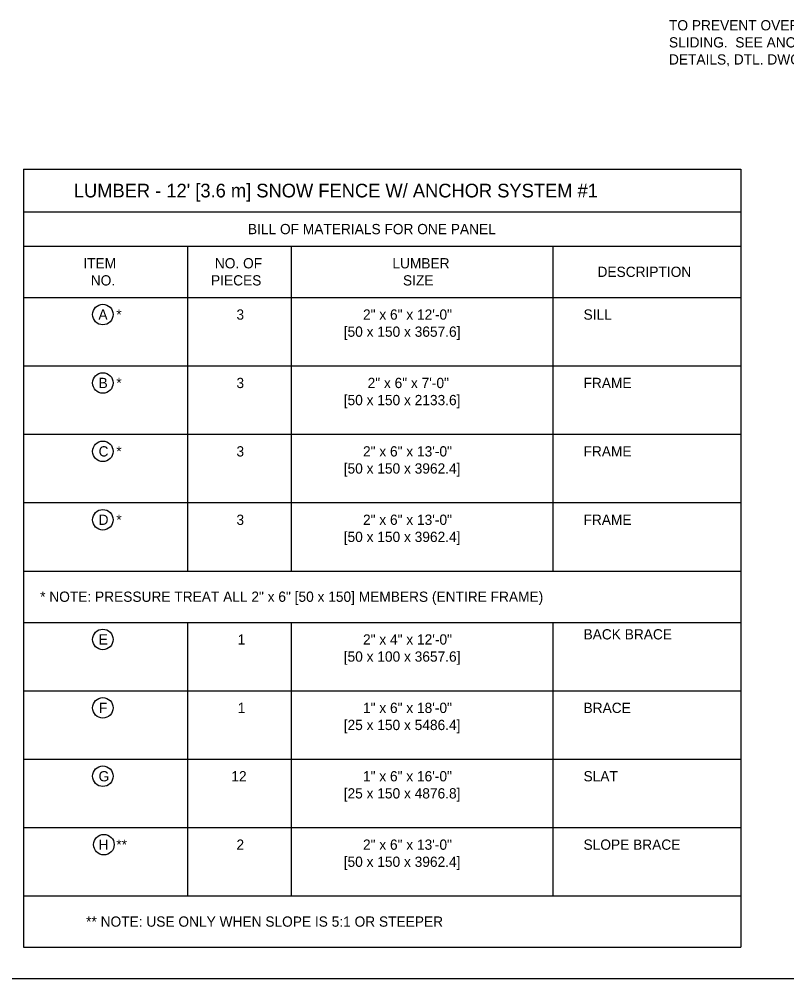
# Model space of a CAD drawing. Extents: x 49991.4 to 50021, y 49987.6 to 50011.4.
# Drawn here: x 50005.06 to 50009.55, y 49987.8 to 49993.41 of the extents above; entities that cross this region are included whole.
import ezdxf

# ---------------------------------------------------------------- set-up
doc = ezdxf.new("R2010")
doc.units = 0
doc.layers.add('Level 1', color=7, linetype='Continuous')
doc.layers.add('Level 2', color=7, linetype='Continuous')

msp = doc.modelspace()

# ---------------------------------------------------------------- linework, layer by layer
at = {"layer": 'Level 1'}
msp.add_lwpolyline([(49999.3835, 49998.9992), (50016.7501, 49998.9992), (50016.7501, 49987.7988), (49999.3835, 49987.7988)], close=True, dxfattribs=at)
at = {"layer": 'Level 2'}
for p, q in [((50005.0866, 49992.5334), (50005.0866, 49987.9834)), ((50005.0866, 49992.5334), (50009.2816, 49992.5334)), ((50009.2816, 49992.5334), (50009.2816, 49987.9834)), ((50005.0866, 49992.2834), (50009.2816, 49992.2834)), ((50005.0866, 49992.0834), (50009.2816, 49992.0834)), ((50006.0473, 49992.0834), (50006.0473, 49990.1834)), ((50006.6522, 49992.0834), (50006.6522, 49990.1834)), ((50008.1833, 49992.0834), (50008.1833, 49990.1834)), ((50005.0866, 49991.7834), (50009.2816, 49991.7834)), ((50005.0866, 49991.3834), (50009.2816, 49991.3834)), ((50005.0866, 49990.9834), (50009.2816, 49990.9834)), ((50005.0866, 49990.5834), (50009.2816, 49990.5834)), ((50005.0866, 49990.1834), (50009.2816, 49990.1834)), ((50005.0866, 49989.8834), (50009.2816, 49989.8834)), ((50006.0473, 49989.8834), (50006.0473, 49988.2834)), ((50006.6522, 49989.8834), (50006.6522, 49988.2834)), ((50008.1833, 49989.8834), (50008.1833, 49988.2834)), ((50005.0866, 49989.4834), (50009.2816, 49989.4834)), ((50005.0866, 49989.0834), (50009.2816, 49989.0834)), ((50005.0866, 49988.6834), (50009.2816, 49988.6834)), ((50005.0866, 49988.2834), (50009.2816, 49988.2834)), ((50005.0866, 49987.9834), (50009.2816, 49987.9834))]:
    msp.add_line(p, q, dxfattribs=at)
for centre in [(50005.5515, 49991.6834), (50005.5516, 49991.2834), (50005.5516, 49990.8834), (50005.5516, 49990.4834), (50005.5516, 49989.7834), (50005.5516, 49989.3834), (50005.5516, 49988.9834), (50005.5577, 49988.5834)]:
    msp.add_circle(centre, 0.06, dxfattribs=at)

# ---------------------------------------------------------------- texts
for s, height, p in [('TO PREVENT OVERTURNING AND', 0.06, (50008.8615, 49993.3453)), ('SLIDING.  SEE ANCHOR SYSTEM #1', 0.06, (50008.8615, 49993.2453)), ('DETAILS, DTL. DWG. NO. 607-40.', 0.06, (50008.8615, 49993.1453)), ("LUMBER - 12' [3.6 m] SNOW FENCE W/ ANCHOR SYSTEM #1", 0.08, (50005.382, 49992.3684)), ('BILL OF MATERIALS FOR ONE PANEL', 0.06, (50006.3998, 49992.1534)), ('ITEM', 0.06, (50005.4374, 49991.9534)), ('NO. OF', 0.06, (50006.2064, 49991.9534)), ('LUMBER', 0.06, (50007.2444, 49991.9534)), ('DESCRIPTION', 0.06, (50008.4436, 49991.9034)), ('NO.', 0.06, (50005.4807, 49991.8534)), ('PIECES', 0.06, (50006.1839, 49991.8534)), ('SIZE', 0.06, (50007.3063, 49991.8534)), ('A', 0.06, (50005.5257, 49991.6534)), ('*', 0.06, (50005.6303, 49991.6534)), ('3', 0.06, (50006.3327, 49991.6534)), ('2" x 6" x 12\'-0"', 0.06, (50007.0727, 49991.6534)), ('SILL         ', 0.06, (50008.3619, 49991.6534)), ('[50 x 150 x 3657.6]', 0.06, (50006.96, 49991.5534)), ('B', 0.06, (50005.5266, 49991.2534)), ('*', 0.06, (50005.6303, 49991.2534)), ('3', 0.06, (50006.3327, 49991.2534)), ('2" x 6" x 7\'-0"', 0.06, (50007.0996, 49991.2534)), ('FRAME        ', 0.06, (50008.3619, 49991.2534)), ('[50 x 150 x 2133.6]', 0.06, (50006.9599, 49991.1534)), ('C', 0.06, (50005.5266, 49990.8534)), ('*', 0.06, (50005.6303, 49990.8534)), ('3', 0.06, (50006.3327, 49990.8534)), ('2" x 6" x 13\'-0"', 0.06, (50007.0726, 49990.8534)), ('FRAME        ', 0.06, (50008.3619, 49990.8534)), ('[50 x 150 x 3962.4]', 0.06, (50006.9599, 49990.7534)), ('D', 0.06, (50005.5266, 49990.4534)), ('*', 0.06, (50005.6303, 49990.4534)), ('3', 0.06, (50006.3327, 49990.4534)), ('2" x 6" x 13\'-0"', 0.06, (50007.0726, 49990.4534)), ('FRAME        ', 0.06, (50008.3619, 49990.4534)), ('[50 x 150 x 3962.4]', 0.06, (50006.9599, 49990.3534)), ('* NOTE: PRESSURE TREAT ALL 2" x 6" [50 x 150] MEMBERS (ENTIRE FRAME)', 0.06, (50005.1848, 49990.0034)), ('BACK BRACE        ', 0.06, (50008.3619, 49989.7834)), ('E', 0.06, (50005.5268, 49989.7534)), ('1', 0.06, (50006.34, 49989.7534)), ('2" x 4" x 12\'-0"', 0.06, (50007.0727, 49989.7534)), ('[50 x 100 x 3657.6]', 0.06, (50006.96, 49989.6534)), ('F', 0.06, (50005.5281, 49989.3534)), ('1', 0.06, (50006.3401, 49989.3534)), ('1" x 6" x 18\'-0"', 0.06, (50007.0726, 49989.3534)), ('BRACE        ', 0.06, (50008.3619, 49989.3534)), ('[25 x 150 x 5486.4]', 0.06, (50006.9599, 49989.2534)), ('G', 0.06, (50005.5266, 49988.9534)), ('12', 0.06, (50006.3027, 49988.9534)), ('1" x 6" x 16\'-0"', 0.06, (50007.0725, 49988.9534)), ('SLAT         ', 0.06, (50008.3619, 49988.9534)), ('[25 x 150 x 4876.8]', 0.06, (50006.9598, 49988.8534)), ('H', 0.06, (50005.5257, 49988.5534)), ('**', 0.06, (50005.6303, 49988.5534)), ('2', 0.06, (50006.3327, 49988.5534)), ('2" x 6" x 13\'-0"', 0.06, (50007.0725, 49988.5534)), ('SLOPE BRACE  ', 0.06, (50008.3619, 49988.5534)), ('[50 x 150 x 3962.4]', 0.06, (50006.9598, 49988.4534)), ('** NOTE: USE ONLY WHEN SLOPE IS 5:1 OR STEEPER', 0.06, (50005.4538, 49988.1034))]:
    msp.add_text(s, height=height, dxfattribs=at).set_placement(p)

doc.saveas('drawing.dxf')
